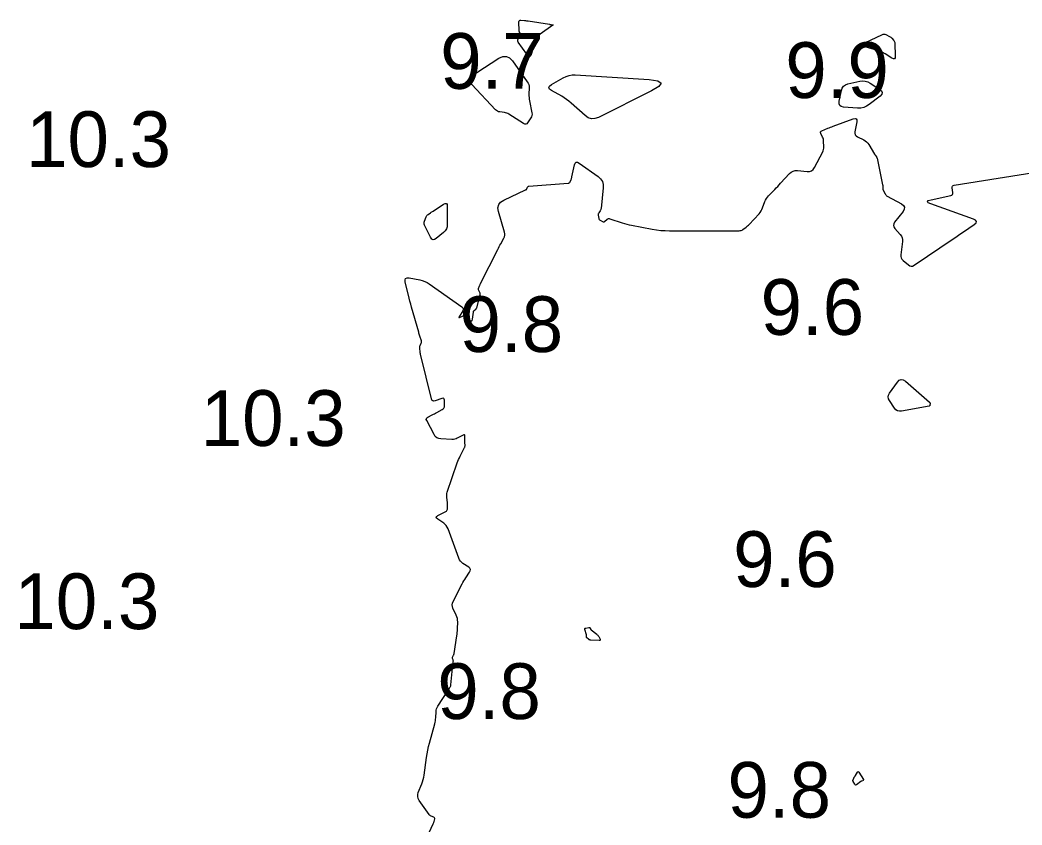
# Model space of a CAD drawing. Extents: x 1023796 to 1112670, y 656573 to 837340.
# Drawn here: x 1100654.8 to 1100744.8, y 689020.5 to 689092.8 of the extents above; entities that cross this region are included whole.
import ezdxf

# ---------------------------------------------------------------- set-up
doc = ezdxf.new("R2010")
doc.units = 0
doc.layers.add('V-CHAN-CONT-10FT', color=7, linetype='Continuous')
doc.layers.add('V-TOPO-SOUN', color=7, linetype='Continuous')

msp = doc.modelspace()

# ---------------------------------------------------------------- linework, layer by layer
at = {"layer": 'V-CHAN-CONT-10FT'}
for points in [[(1100700.293, 689092.712), (1100700.376, 689092.7), (1100700.46, 689092.688), (1100702.366, 689092.389), (1100702.402, 689092.383), (1100702.438, 689092.378), (1100702.474, 689092.373), (1100702.51, 689092.369), (1100702.654, 689092.352), (1100702.681, 689092.345), (1100702.693, 689092.335), (1100702.688, 689092.32), (1100702.666, 689092.302), (1100701.532, 689091.516), (1100701.35, 689091.366), (1100701.203, 689091.192), (1100701.091, 689090.993), (1100701.014, 689090.771), (1100700.758, 689089.775), (1100700.685, 689089.587), (1100700.591, 689089.511), (1100700.476, 689089.548), (1100700.341, 689089.698), (1100699.563, 689090.795), (1100699.525, 689090.865), (1100699.51, 689090.936), (1100699.518, 689091.008), (1100699.548, 689091.081), (1100699.766, 689091.465), (1100699.778, 689091.494), (1100699.78, 689091.523), (1100699.774, 689091.55), (1100699.758, 689091.577), (1100699.675, 689091.684), (1100699.656, 689091.712), (1100699.643, 689091.741), (1100699.635, 689091.772), (1100699.632, 689091.805), (1100699.624, 689092.624), (1100699.633, 689092.697), (1100699.664, 689092.746), (1100699.716, 689092.771), (1100699.79, 689092.773), (1100700.125, 689092.734), (1100700.209, 689092.723)], [(1100733.341, 689090.823), (1100733.358, 689090.762), (1100733.365, 689090.698), (1100733.404, 689089.517), (1100733.39, 689089.368), (1100733.335, 689089.291), (1100733.241, 689089.284), (1100733.106, 689089.349), (1100732.487, 689089.75), (1100732.329, 689089.843), (1100732.166, 689089.925), (1100731.997, 689089.993), (1100731.822, 689090.049), (1100730.696, 689090.361), (1100730.509, 689090.434), (1100730.441, 689090.519), (1100730.493, 689090.614), (1100730.664, 689090.719), (1100732.244, 689091.478), (1100732.322, 689091.506), (1100732.4, 689091.515), (1100732.477, 689091.504), (1100732.554, 689091.475), (1100732.899, 689091.3), (1100732.956, 689091.268), (1100733.01, 689091.23), (1100733.059, 689091.186), (1100733.104, 689091.138), (1100733.275, 689090.933), (1100733.313, 689090.88)], [(1100700.494, 689086.98), (1100700.524, 689086.844), (1100700.531, 689086.701), (1100700.516, 689086.116), (1100700.516, 689085.97), (1100700.525, 689085.825), (1100700.541, 689085.681), (1100700.566, 689085.537), (1100700.782, 689084.455), (1100700.795, 689084.329), (1100700.784, 689084.208), (1100700.748, 689084.093), (1100700.687, 689083.982), (1100700.396, 689083.549), (1100700.318, 689083.463), (1100700.232, 689083.421), (1100700.136, 689083.425), (1100700.03, 689083.473), (1100698.716, 689084.319), (1100698.623, 689084.372), (1100698.526, 689084.414), (1100698.425, 689084.445), (1100698.319, 689084.466), (1100697.89, 689084.525), (1100697.787, 689084.548), (1100697.692, 689084.587), (1100697.605, 689084.641), (1100697.527, 689084.712), (1100695.387, 689086.981), (1100695.325, 689087.066), (1100695.297, 689087.155), (1100695.3, 689087.248), (1100695.337, 689087.346), (1100695.548, 689087.747), (1100695.606, 689087.842), (1100695.675, 689087.928), (1100695.754, 689088.004), (1100695.844, 689088.07), (1100697.822, 689089.342), (1100698.17, 689089.501), (1100698.489, 689089.515), (1100698.779, 689089.383), (1100699.042, 689089.105), (1100700.369, 689087.233), (1100700.443, 689087.11)], [(1100703.904, 689085.655), (1100703.687, 689085.802), (1100703.462, 689085.937), (1100702.544, 689086.455), (1100702.371, 689086.584), (1100702.313, 689086.715), (1100702.369, 689086.846), (1100702.54, 689086.979), (1100703.594, 689087.593), (1100703.85, 689087.719), (1100704.116, 689087.804), (1100704.392, 689087.848), (1100704.678, 689087.851), (1100711.317, 689087.44), (1100712.087, 689087.329), (1100712.378, 689087.121), (1100712.191, 689086.817), (1100711.525, 689086.415), (1100706.751, 689084.039), (1100706.43, 689083.926), (1100706.123, 689083.917), (1100705.83, 689084.009), (1100705.551, 689084.204), (1100704.312, 689085.325), (1100704.112, 689085.496)], [(1100730.698, 689087.296), (1100730.928, 689087.229), (1100731.149, 689087.113), (1100732.016, 689086.552), (1100732.181, 689086.41), (1100732.24, 689086.263), (1100732.194, 689086.11), (1100732.044, 689085.954), (1100731.067, 689085.189), (1100730.83, 689085.034), (1100730.576, 689084.929), (1100730.308, 689084.874), (1100730.024, 689084.87), (1100728.768, 689084.959), (1100728.558, 689085.005), (1100728.422, 689085.106), (1100728.361, 689085.265), (1100728.373, 689085.479), (1100728.571, 689086.449), (1100728.644, 689086.668), (1100728.766, 689086.84), (1100728.935, 689086.965), (1100729.153, 689087.042), (1100730.212, 689087.281), (1100730.46, 689087.313)], [(1100691.796, 689075.555), (1100691.852, 689075.593), (1100691.909, 689075.63), (1100692.841, 689076.236), (1100692.994, 689076.309), (1100693.103, 689076.302), (1100693.168, 689076.214), (1100693.19, 689076.046), (1100693.19, 689074.418), (1100693.169, 689074.213), (1100693.107, 689074.027), (1100693.004, 689073.86), (1100692.86, 689073.712), (1100692.2, 689073.161), (1100692.044, 689073.065), (1100691.906, 689073.051), (1100691.786, 689073.121), (1100691.684, 689073.273), (1100691.156, 689074.374), (1100691.124, 689074.46), (1100691.111, 689074.546), (1100691.118, 689074.633), (1100691.142, 689074.721), (1100691.299, 689075.122), (1100691.328, 689075.182), (1100691.364, 689075.236), (1100691.408, 689075.284), (1100691.46, 689075.325), (1100691.683, 689075.479), (1100691.739, 689075.518)], [(1100736.514, 689058.428), (1100736.523, 689058.396), (1100736.524, 689058.361), (1100736.515, 689058.212), (1100736.508, 689058.179), (1100736.493, 689058.154), (1100736.469, 689058.136), (1100736.437, 689058.125), (1100733.972, 689057.677), (1100733.783, 689057.666), (1100733.615, 689057.706), (1100733.468, 689057.798), (1100733.344, 689057.941), (1100732.888, 689058.616), (1100732.803, 689058.785), (1100732.776, 689058.952), (1100732.807, 689059.12), (1100732.896, 689059.286), (1100733.6, 689060.278), (1100733.763, 689060.449), (1100733.937, 689060.52), (1100734.124, 689060.491), (1100734.322, 689060.363), (1100736.473, 689058.483), (1100736.497, 689058.457)], [(1100706.702, 689037.551), (1100706.742, 689037.496), (1100706.777, 689037.438), (1100706.905, 689037.195), (1100706.924, 689037.142), (1100706.919, 689037.105), (1100706.888, 689037.084), (1100706.832, 689037.079), (1100706.073, 689037.115), (1100706.024, 689037.122), (1100705.978, 689037.136), (1100705.935, 689037.158), (1100705.896, 689037.187), (1100705.698, 689037.363), (1100705.685, 689037.377), (1100705.677, 689037.393), (1100705.673, 689037.41), (1100705.673, 689037.429), (1100705.682, 689037.508), (1100705.683, 689037.528), (1100705.682, 689037.547), (1100705.679, 689037.567), (1100705.675, 689037.586), (1100705.53, 689038.063), (1100705.522, 689038.115), (1100705.533, 689038.155), (1100705.563, 689038.184), (1100705.612, 689038.202), (1100705.908, 689038.266), (1100705.933, 689038.268), (1100705.955, 689038.262), (1100705.974, 689038.249), (1100705.989, 689038.228), (1100706.043, 689038.129), (1100706.058, 689038.106), (1100706.074, 689038.083), (1100706.093, 689038.063), (1100706.114, 689038.045), (1100706.606, 689037.646), (1100706.656, 689037.601)], [(1100730.545, 689024.595), (1100730.544, 689024.584), (1100730.539, 689024.573), (1100730.514, 689024.53), (1100730.507, 689024.52), (1100730.499, 689024.511), (1100730.489, 689024.504), (1100730.478, 689024.499), (1100730.387, 689024.466), (1100730.369, 689024.459), (1100730.351, 689024.45), (1100730.334, 689024.44), (1100730.317, 689024.428), (1100729.928, 689024.143), (1100729.881, 689024.118), (1100729.839, 689024.115), (1100729.801, 689024.136), (1100729.769, 689024.178), (1100729.627, 689024.439), (1100729.613, 689024.472), (1100729.607, 689024.505), (1100729.609, 689024.538), (1100729.619, 689024.572), (1100729.683, 689024.732), (1100729.693, 689024.754), (1100729.704, 689024.776), (1100729.716, 689024.796), (1100729.729, 689024.816), (1100729.784, 689024.895), (1100729.798, 689024.915), (1100729.811, 689024.935), (1100729.824, 689024.955), (1100729.837, 689024.975), (1100730.008, 689025.263), (1100730.04, 689025.304), (1100730.073, 689025.318), (1100730.106, 689025.305), (1100730.14, 689025.264), (1100730.538, 689024.616), (1100730.543, 689024.605)]]:
    msp.add_lwpolyline(points, close=True, dxfattribs=at)
msp.add_lwpolyline([(1100691.088, 689018.795), (1100691.931, 689020.632), (1100691.954, 689020.684), (1100691.974, 689020.738), (1100691.991, 689020.792), (1100692.005, 689020.848), (1100692.058, 689021.071), (1100692.063, 689021.123), (1100692.051, 689021.165), (1100692.022, 689021.199), (1100691.977, 689021.223), (1100691.739, 689021.312), (1100691.685, 689021.338), (1100691.636, 689021.37), (1100691.592, 689021.41), (1100691.554, 689021.457), (1100690.666, 689022.735), (1100690.573, 689022.907), (1100690.528, 689023.085), (1100690.532, 689023.268), (1100690.585, 689023.456), (1100690.892, 689024.221), (1100690.963, 689024.414), (1100691.022, 689024.61), (1100691.069, 689024.809), (1100691.103, 689025.011), (1100691.323, 689026.582), (1100691.375, 689026.911), (1100691.436, 689027.237), (1100691.508, 689027.562), (1100691.59, 689027.884), (1100692.058, 689029.613), (1100692.091, 689029.746), (1100692.116, 689029.88), (1100692.134, 689030.016), (1100692.145, 689030.152), (1100692.175, 689030.7), (1100692.191, 689030.835), (1100692.224, 689030.964), (1100692.274, 689031.087), (1100692.34, 689031.204), (1100693.229, 689032.562), (1100693.258, 689032.606), (1100693.286, 689032.651), (1100693.314, 689032.696), (1100693.341, 689032.741), (1100693.448, 689032.922), (1100693.472, 689032.969), (1100693.491, 689033.017), (1100693.505, 689033.066), (1100693.513, 689033.118), (1100693.729, 689035.217), (1100693.731, 689035.249), (1100693.729, 689035.28), (1100693.722, 689035.311), (1100693.713, 689035.341), (1100693.666, 689035.46), (1100693.657, 689035.49), (1100693.655, 689035.52), (1100693.659, 689035.549), (1100693.669, 689035.578), (1100693.755, 689035.764), (1100693.772, 689035.806), (1100693.786, 689035.848), (1100693.797, 689035.891), (1100693.806, 689035.935), (1100694.048, 689037.492), (1100694.07, 689037.65), (1100694.086, 689037.808), (1100694.098, 689037.966), (1100694.104, 689038.125), (1100694.119, 689038.762), (1100694.113, 689038.919), (1100694.09, 689039.072), (1100694.049, 689039.222), (1100693.989, 689039.367), (1100693.693, 689039.987), (1100693.64, 689040.138), (1100693.624, 689040.288), (1100693.645, 689040.438), (1100693.703, 689040.587), (1100694.518, 689042.16), (1100694.592, 689042.299), (1100694.671, 689042.435), (1100694.753, 689042.569), (1100694.839, 689042.701), (1100695.192, 689043.225), (1100695.253, 689043.35), (1100695.259, 689043.464), (1100695.21, 689043.567), (1100695.107, 689043.659), (1100694.586, 689044.008), (1100694.465, 689044.103), (1100694.363, 689044.213), (1100694.281, 689044.337), (1100694.217, 689044.477), (1100693.251, 689047.123), (1100693.186, 689047.267), (1100693.1, 689047.396), (1100692.995, 689047.509), (1100692.87, 689047.606), (1100692.325, 689047.967), (1100692.226, 689048.053), (1100692.196, 689048.136), (1100692.234, 689048.215), (1100692.341, 689048.291), (1100693.058, 689048.671), (1100693.113, 689048.709), (1100693.154, 689048.756), (1100693.181, 689048.813), (1100693.193, 689048.879), (1100693.213, 689049.161), (1100693.216, 689049.232), (1100693.216, 689049.303), (1100693.213, 689049.373), (1100693.206, 689049.444), (1100693.146, 689049.959), (1100693.139, 689050.068), (1100693.144, 689050.175), (1100693.161, 689050.282), (1100693.191, 689050.387), (1100694.087, 689053.021), (1100694.142, 689053.176), (1100694.203, 689053.328), (1100694.27, 689053.478), (1100694.342, 689053.625), (1100694.74, 689054.402), (1100694.762, 689054.453), (1100694.777, 689054.506), (1100694.784, 689054.56), (1100694.783, 689054.615), (1100694.767, 689054.84), (1100694.763, 689054.897), (1100694.761, 689054.953), (1100694.759, 689055.009), (1100694.758, 689055.066), (1100694.758, 689055.44), (1100694.749, 689055.506), (1100694.722, 689055.543), (1100694.677, 689055.55), (1100694.614, 689055.526), (1100694.086, 689055.246), (1100693.973, 689055.195), (1100693.855, 689055.16), (1100693.734, 689055.141), (1100693.609, 689055.139), (1100692.613, 689055.185), (1100692.418, 689055.216), (1100692.251, 689055.291), (1100692.112, 689055.41), (1100692.001, 689055.572), (1100691.337, 689056.823), (1100691.303, 689056.918), (1100691.307, 689057.001), (1100691.351, 689057.071), (1100691.432, 689057.13), (1100691.837, 689057.34), (1100691.939, 689057.393), (1100692.04, 689057.445), (1100692.141, 689057.499), (1100692.241, 689057.552), (1100692.721, 689057.806), (1100692.815, 689057.871), (1100692.881, 689057.952), (1100692.922, 689058.049), (1100692.935, 689058.162), (1100692.935, 689058.647), (1100692.921, 689058.749), (1100692.878, 689058.809), (1100692.807, 689058.829), (1100692.707, 689058.809), (1100692.108, 689058.595), (1100691.983, 689058.57), (1100691.884, 689058.593), (1100691.811, 689058.663), (1100691.763, 689058.781), (1100690.808, 689062.657), (1100690.79, 689062.734), (1100690.776, 689062.812), (1100690.764, 689062.891), (1100690.755, 689062.97), (1100690.72, 689063.329), (1100690.718, 689063.387), (1100690.723, 689063.443), (1100690.735, 689063.499), (1100690.754, 689063.553), (1100690.845, 689063.768), (1100690.863, 689063.822), (1100690.871, 689063.876), (1100690.869, 689063.931), (1100690.857, 689063.987), (1100690.726, 689064.41), (1100690.699, 689064.499), (1100690.673, 689064.588), (1100690.646, 689064.677), (1100690.621, 689064.767), (1100689.983, 689067.018), (1100689.908, 689067.286), (1100689.836, 689067.555), (1100689.766, 689067.824), (1100689.699, 689068.095), (1100689.415, 689069.252), (1100689.395, 689069.45), (1100689.447, 689069.578), (1100689.573, 689069.637), (1100689.772, 689069.627), (1100690.713, 689069.448), (1100690.943, 689069.391), (1100691.164, 689069.312), (1100691.374, 689069.209), (1100691.575, 689069.083), (1100694.504, 689067.027), (1100694.585, 689066.95), (1100694.625, 689066.865), (1100694.621, 689066.771), (1100694.575, 689066.669), (1100694.244, 689066.147), (1100694.22, 689066.1), (1100694.22, 689066.073), (1100694.246, 689066.069), (1100694.297, 689066.086), (1100694.551, 689066.198), (1100694.614, 689066.217), (1100694.674, 689066.219), (1100694.732, 689066.203), (1100694.789, 689066.169), (1100695.238, 689065.822), (1100695.322, 689065.773), (1100695.385, 689065.772), (1100695.429, 689065.818), (1100695.452, 689065.912), (1100695.527, 689066.559), (1100695.536, 689066.6), (1100695.551, 689066.637), (1100695.574, 689066.671), (1100695.603, 689066.7), (1100695.736, 689066.81), (1100695.767, 689066.839), (1100695.792, 689066.872), (1100695.811, 689066.908), (1100695.825, 689066.948), (1100696.142, 689068.119), (1100696.151, 689068.17), (1100696.15, 689068.22), (1100696.138, 689068.268), (1100696.116, 689068.315), (1100696.009, 689068.5), (1100695.988, 689068.547), (1100695.979, 689068.594), (1100695.981, 689068.643), (1100695.994, 689068.692), (1100696.082, 689068.916), (1100696.104, 689068.97), (1100696.127, 689069.023), (1100696.151, 689069.076), (1100696.177, 689069.128), (1100697.718, 689072.184), (1100697.784, 689072.313), (1100697.851, 689072.441), (1100697.918, 689072.569), (1100697.987, 689072.696), (1100698.265, 689073.202), (1100698.321, 689073.33), (1100698.349, 689073.462), (1100698.35, 689073.596), (1100698.324, 689073.733), (1100697.787, 689075.596), (1100697.739, 689075.927), (1100697.801, 689076.208), (1100697.973, 689076.439), (1100698.256, 689076.619), (1100700.223, 689077.52), (1100700.257, 689077.54), (1100700.285, 689077.564), (1100700.309, 689077.594), (1100700.327, 689077.628), (1100700.39, 689077.777), (1100700.408, 689077.81), (1100700.433, 689077.835), (1100700.464, 689077.851), (1100700.502, 689077.858), (1100704.035, 689078.12), (1100704.092, 689078.132), (1100704.139, 689078.155), (1100704.177, 689078.192), (1100704.205, 689078.242), (1100704.301, 689078.467), (1100704.324, 689078.524), (1100704.344, 689078.582), (1100704.36, 689078.64), (1100704.375, 689078.7), (1100704.603, 689079.778), (1100704.66, 689079.938), (1100704.749, 689080.019), (1100704.869, 689080.02), (1100705.02, 689079.942), (1100706.725, 689078.738), (1100706.955, 689078.532), (1100707.109, 689078.292), (1100707.187, 689078.017), (1100707.19, 689077.708), (1100706.993, 689075.868), (1100706.984, 689075.812), (1100706.968, 689075.758), (1100706.946, 689075.707), (1100706.917, 689075.658), (1100706.79, 689075.466), (1100706.763, 689075.417), (1100706.746, 689075.366), (1100706.739, 689075.312), (1100706.741, 689075.256), (1100706.778, 689074.974), (1100706.792, 689074.918), (1100706.817, 689074.87), (1100706.853, 689074.83), (1100706.901, 689074.798), (1100707.115, 689074.686), (1100707.168, 689074.666), (1100707.219, 689074.663), (1100707.268, 689074.676), (1100707.315, 689074.707), (1100707.545, 689074.897), (1100707.601, 689074.933), (1100707.659, 689074.953), (1100707.721, 689074.955), (1100707.785, 689074.941), (1100708.884, 689074.567), (1100709.09, 689074.501), (1100709.299, 689074.443), (1100709.509, 689074.392), (1100709.721, 689074.349), (1100711.593, 689074.004), (1100711.977, 689073.942), (1100712.362, 689073.898), (1100712.75, 689073.872), (1100713.138, 689073.863), (1100719.401, 689073.863), (1100719.488, 689073.87), (1100719.571, 689073.89), (1100719.65, 689073.923), (1100719.724, 689073.969), (1100720.012, 689074.182), (1100720.082, 689074.236), (1100720.15, 689074.294), (1100720.214, 689074.355), (1100720.276, 689074.419), (1100721.172, 689075.394), (1100721.27, 689075.511), (1100721.355, 689075.635), (1100721.428, 689075.767), (1100721.488, 689075.907), (1100721.705, 689076.482), (1100721.766, 689076.621), (1100721.84, 689076.753), (1100721.927, 689076.875), (1100722.027, 689076.99), (1100722.595, 689077.577), (1100722.725, 689077.712), (1100722.854, 689077.848), (1100722.982, 689077.985), (1100723.108, 689078.123), (1100723.895, 689078.987), (1100724.052, 689079.127), (1100724.226, 689079.22), (1100724.418, 689079.267), (1100724.628, 689079.268), (1100725.503, 689079.179), (1100725.707, 689079.184), (1100725.883, 689079.243), (1100726.029, 689079.356), (1100726.146, 689079.524), (1100726.89, 689080.938), (1100726.939, 689081.045), (1100726.972, 689081.155), (1100726.99, 689081.269), (1100726.993, 689081.387), (1100726.973, 689081.917), (1100726.965, 689082.008), (1100726.948, 689082.096), (1100726.921, 689082.182), (1100726.885, 689082.266), (1100726.724, 689082.596), (1100726.699, 689082.673), (1100726.706, 689082.738), (1100726.743, 689082.791), (1100726.813, 689082.832), (1100727.36, 689083.057), (1100727.479, 689083.106), (1100727.599, 689083.153), (1100727.72, 689083.2), (1100727.841, 689083.245), (1100729.637, 689083.904), (1100729.8, 689083.941), (1100729.906, 689083.91), (1100729.954, 689083.811), (1100729.946, 689083.644), (1100729.782, 689082.751), (1100729.774, 689082.606), (1100729.809, 689082.482), (1100729.887, 689082.379), (1100730.007, 689082.297), (1100730.572, 689082.011), (1100730.705, 689081.932), (1100730.825, 689081.836), (1100730.929, 689081.725), (1100731.019, 689081.598), (1100731.553, 689080.725), (1100731.571, 689080.696), (1100731.59, 689080.668), (1100731.61, 689080.64), (1100731.63, 689080.613), (1100731.713, 689080.504), (1100731.732, 689080.476), (1100731.747, 689080.447), (1100731.759, 689080.416), (1100731.768, 689080.383), (1100732.268, 689077.995), (1100732.275, 689077.953), (1100732.281, 689077.912), (1100732.284, 689077.87), (1100732.285, 689077.827), (1100732.285, 689077.658), (1100732.287, 689077.617), (1100732.295, 689077.576), (1100732.307, 689077.537), (1100732.324, 689077.499), (1100732.491, 689077.175), (1100732.53, 689077.113), (1100732.576, 689077.058), (1100732.629, 689077.01), (1100732.691, 689076.97), (1100733.964, 689076.265), (1100734.146, 689076.126), (1100734.23, 689075.967), (1100734.215, 689075.788), (1100734.101, 689075.589), (1100733.346, 689074.619), (1100733.263, 689074.478), (1100733.239, 689074.338), (1100733.274, 689074.201), (1100733.366, 689074.066), (1100733.852, 689073.53), (1100733.956, 689073.39), (1100734.023, 689073.239), (1100734.054, 689073.077), (1100734.049, 689072.903), (1100733.897, 689071.713), (1100733.894, 689071.563), (1100733.927, 689071.426), (1100733.995, 689071.304), (1100734.099, 689071.195), (1100734.584, 689070.789), (1100734.706, 689070.711), (1100734.831, 689070.681), (1100734.959, 689070.698), (1100735.088, 689070.763), (1100738.597, 689073.141), (1100738.832, 689073.3), (1100739.067, 689073.459), (1100739.302, 689073.618), (1100739.537, 689073.776), (1100740.479, 689074.409), (1100740.652, 689074.56), (1100740.699, 689074.694), (1100740.62, 689074.813), (1100740.415, 689074.916), (1100736.598, 689076.267), (1100736.359, 689076.376), (1100736.283, 689076.474), (1100736.371, 689076.563), (1100736.621, 689076.641), (1100738.406, 689077.037), (1100738.494, 689077.07), (1100738.552, 689077.123), (1100738.58, 689077.197), (1100738.577, 689077.291), (1100738.506, 689077.707), (1100738.503, 689077.8), (1100738.531, 689077.871), (1100738.59, 689077.921), (1100738.679, 689077.948), (1100747.16, 689079.304)], dxfattribs=at)

# ---------------------------------------------------------------- texts
at = {"layer": 'V-TOPO-SOUN'}
for s, p in [('9.7', (1100692.552, 689086.6)), ('9.9', (1100723.532, 689085.78)), ('10.3 ', (1100655.372, 689079.58)), ('9.6', (1100721.314, 689064.52)), ('9.8', (1100694.292, 689062.98)), ('10.3 ', (1100671.052, 689054.55)), ('9.6', (1100718.854, 689041.89)), ('10.3 ', (1100654.322, 689038.11)), ('9.8', (1100692.292, 689030.04)), ('9.8', (1100718.342, 689021.18))]:
    msp.add_text(s, height=5, dxfattribs=at).set_placement(p)

doc.saveas('drawing.dxf')
